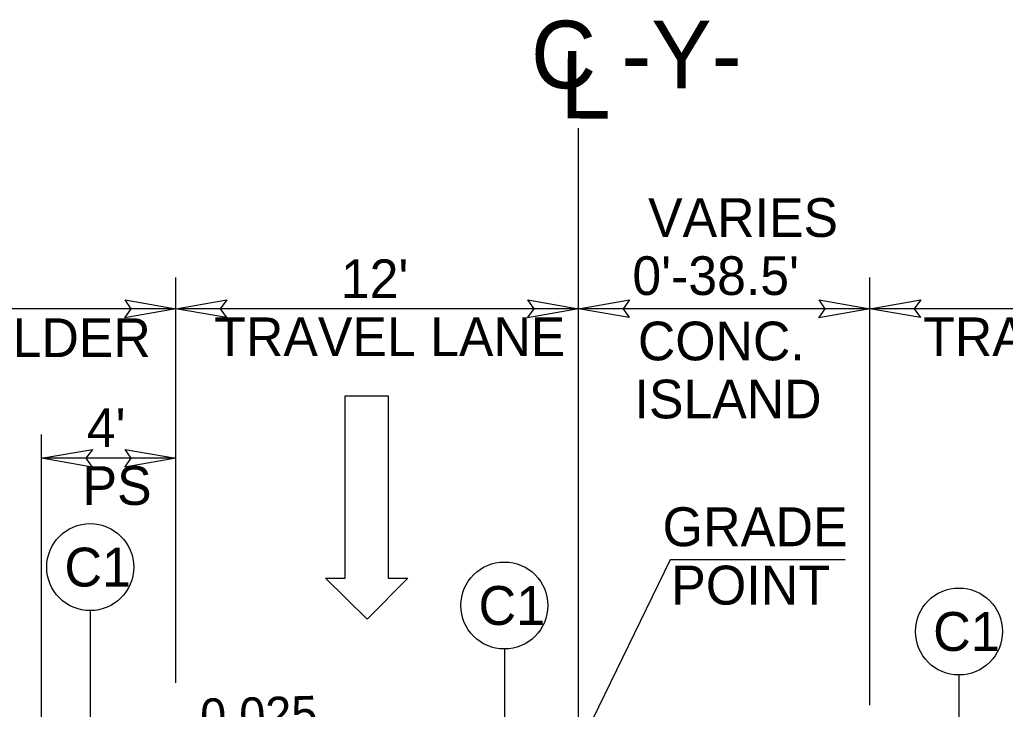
# Model space of a CAD drawing. Extents: x 2176024 to 2177225, y 75947 to 76635.
# Drawn here: x 2176189.73 to 2176219.09, y 76477.51 to 76498.07 of the extents above; entities that cross this region are included whole.
import ezdxf

# ---------------------------------------------------------------- set-up
doc = ezdxf.new("R2010")
doc.units = 0
for name, color, linetype in [('Old_Level_11', 7, 'Continuous'), ('Old_Level_4', 7, 'Continuous'), ('Prop Dimension', 7, 'Continuous'), ('Typical Pavement Slope Information CELL', 7, 'Continuous'), ('Typical Terminator CELL', 7, 'Continuous'), ('Typical Text General CELL', 7, 'Continuous'), ('Typical Text Label CELL', 7, 'Continuous')]:
    doc.layers.add(name, color=color, linetype=linetype)

msp = doc.modelspace()

# ---------------------------------------------------------------- linework, layer by layer
at = {"layer": 'Old_Level_11'}
for p, q in [((2176209.098, 76481.967), (2176206.375, 76476.358)), ((2176214.317, 76481.967), (2176209.098, 76481.967)), ((2176191.827, 76480.452), (2176191.827, 76476.149)), ((2176204.164, 76479.308), (2176204.164, 76476.175)), ((2176217.706, 76478.533), (2176217.706, 76475.729))]:
    msp.add_line(p, q, dxfattribs=at)
for centre in [(2176191.827, 76481.748), (2176204.164, 76480.604), (2176217.706, 76479.829)]:
    msp.add_circle(centre, 1.296, dxfattribs=at)
at = {"layer": 'Old_Level_4'}
for p, q in [((2176199.422, 76481.418), (2176199.422, 76486.85)), ((2176199.422, 76486.85), (2176200.702, 76486.85)), ((2176200.702, 76486.85), (2176200.702, 76481.418)), ((2176200.081, 76480.195), (2176198.84, 76481.418)), ((2176198.84, 76481.418), (2176199.422, 76481.418)), ((2176201.284, 76481.418), (2176200.081, 76480.195)), ((2176200.702, 76481.418), (2176201.284, 76481.418))]:
    msp.add_line(p, q, dxfattribs=at)
at = {"layer": 'Prop Dimension'}
for p, q in [((2176206.375, 76490.249), (2176206.375, 76494.834)), ((2176194.375, 76478.298), (2176194.375, 76490.379)), ((2176215.05, 76477.714), (2176215.05, 76490.379)), ((2176215.05, 76477.638), (2176215.05, 76490.336)), ((2176206.375, 76486.866), (2176206.375, 76490.249)), ((2176194.375, 76489.451), (2176184.375, 76489.451)), ((2176206.375, 76489.451), (2176194.481, 76489.451)), ((2176215.05, 76489.451), (2176206.375, 76489.451)), ((2176227.05, 76489.451), (2176215.05, 76489.451)), ((2176206.375, 76468.419), (2176206.375, 76486.866)), ((2176190.375, 76476.625), (2176190.375, 76485.701)), ((2176194.375, 76484.991), (2176190.375, 76484.991))]:
    msp.add_line(p, q, dxfattribs=at)
at = {"layer": 'Typical Terminator CELL'}
for points in [[(2176192.865, 76489.711), (2176194.375, 76489.451), (2176192.857, 76489.183), (2176193.05, 76489.451)], [(2176195.884, 76489.191), (2176194.375, 76489.451), (2176195.893, 76489.72), (2176195.7, 76489.451)], [(2176204.865, 76489.711), (2176206.375, 76489.451), (2176204.857, 76489.183), (2176205.05, 76489.451)], [(2176207.884, 76489.191), (2176206.375, 76489.451), (2176207.893, 76489.72), (2176207.7, 76489.451)], [(2176213.54, 76489.711), (2176215.05, 76489.451), (2176213.532, 76489.183), (2176213.725, 76489.451)], [(2176216.56, 76489.191), (2176215.05, 76489.451), (2176216.568, 76489.72), (2176216.375, 76489.451)], [(2176191.884, 76484.731), (2176190.375, 76484.991), (2176191.893, 76485.259), (2176191.7, 76484.991)], [(2176192.865, 76485.251), (2176194.375, 76484.991), (2176192.857, 76484.723), (2176193.05, 76484.991)]]:
    msp.add_lwpolyline(points, close=True, dxfattribs=at)

# ---------------------------------------------------------------- texts
at = {"layer": 'Old_Level_11'}
for s, rotation, p in [('GRADE', 0.0002, (2176208.876, 76482.371)), ('C1', 0.0003, (2176191.058, 76481.168)), ('POINT', 0.0002, (2176209.13, 76480.631)), ('C1', 0.0003, (2176203.395, 76480.024)), ('C1', 0.0003, (2176216.937, 76479.249))]:
    msp.add_text(s, height=1.16, rotation=rotation, dxfattribs=at).set_placement(p)
at = {"layer": 'Typical Pavement Slope Information CELL'}
msp.add_text('0.025', height=1.0429, rotation=1.4932, dxfattribs=at).set_placement((2176195.119, 76476.783))
at = {"layer": 'Typical Text General CELL'}
for s, height, p in [('VARIES', 1.1533, (2176208.446, 76491.59)), ("12'", 1.1533, (2176199.293, 76489.767)), ("0'-38.5'", 1.1533, (2176207.978, 76489.86)), ('SHOULDER', 1.1533, (2176185.061, 76488.01)), ('TRAVEL LANE', 1.15334, (2176195.524, 76488.037)), ('TRAVEL LANE', 1.15334, (2176216.641, 76488.037)), ('CONC.', 1.1533, (2176208.142, 76487.912)), ('ISLAND', 1.1533, (2176208.042, 76486.182)), ("4' ", 1.1533, (2176191.727, 76485.332)), ('PS', 1.1533, (2176191.598, 76483.602))]:
    msp.add_text(s, height=height, dxfattribs=at).set_placement(p)
at = {"layer": 'Typical Text Label CELL'}
msp.add_text('C -Y- ', height=2.0131, dxfattribs=at).set_placement((2176204.954, 76496.022))
msp.add_text('L', height=2.013, rotation=359.9469, dxfattribs=at).set_placement((2176205.832, 76495.121))

doc.saveas('drawing.dxf')
